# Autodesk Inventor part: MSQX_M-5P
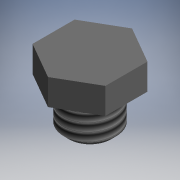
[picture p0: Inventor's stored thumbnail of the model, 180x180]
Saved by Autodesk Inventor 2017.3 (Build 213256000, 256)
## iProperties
Part Number: MSQX_M-5P
Material: Generic
Catalog Web Link: www.cadenas.de
Description: MSQX M-5P-Low-Speed Rotary Table Rack & Pinion Style
Vendor: SMC
Document SubType Name: Modeling
Designer: partserver
Manufacturer: SMC
Mass: 0.178699 g
Surface Area: 1.99414 cm^2
Volume: 0.178699 cm^3
Density: 1 g/cm^3
Appearance: PSOLRGB-128-128-128
Category: PARTsolutions
Company: SMC
Title: M-5P
Author: Cadenas PARTsolutions
Comments: Low-Speed Rotary Table Rack & Pinion Style
PSOL_IDENT_0: {$CADENAS_DATA\23d-libs\smc_jp\actuator\rotary_actuator\msqx\parts\msqx_5p.prj},156 {VTYP=3D},{NB=MS
PSOL_IDENT_1: QX_M-5P},{LINA=M-5P},{NN=MSQX M-5P},{DATE=09.12.2020 02:49:37},{GEOMDATE=19.01.2011 08:34:00},{VERSI
PSOL_IDENT_2: ON=},{LINEID=10},{WBVAR=},{WBNUMERIC=}  {NB=MSQX_M-5P},{LINA=M-5P},{KT=DUMMY},{MODEL=M-5P}
NB: MSQX_M-5P
NN: MSQX M-5P
NT: Low-Speed Rotary Table Rack & Pinion Style
NBSYN: MSQX_$MODEL.
LINA: M-5P
CATALOG: SMC (JP
MODEL: M-5P
SUPPLIER: SMC
ARTICLENO: MSQX_M-5P
BOMINFO: M-5P
CREATOR: CADENAS GmbH
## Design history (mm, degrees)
sketch "Sketch_1"
  geometry: L1 (-3.5, -2.021)-(0, -4.041); L2 (0, -4.041)-(3.5, -2.021); L3 (3.5, -2.021)-(3.5, 2.021); L4 (3.5, 2.021)-(0, 4.041); L5 (0, 4.041)-(-3.5, 2.021); L6 (-3.5, 2.021)-(-3.5, -2.021)
  constraints: 12 end point
extrude "Extrusion1" join sketch "Sketch_1" distance "d0" = 2.7; taper "d1" = 0 deg
sketch "Sketch_4"
  geometry: C1 r 5 at (0, 0); C2 r 3 at (0, 0); 2 further points
  constraints: 2 centre point
extrude "Extrusion2" cut sketch "Sketch_4" distance "d2" = 0.2; taper "d3" = 0 deg
sketch "Sketch_2"
  geometry: L1 (0, 0)-(0, 3.5); L2 (0, 3.5)-(2.01, 3.5); L3 (2.01, 3.5)-(2.5, 3.01); L4 (2.5, 3.01)-(2.5, 0); L5 (2.5, 0)-(0, 0); L6 (0, 0)-(0, 3.5)
  constraints: 12 end point
revolve "Revolution1" sketch "Sketch_2" stored, may be unused: angle "d4" = 360 deg
thread "Thread1" dims "d5" = 3.0095, "d6" = 0
node "plug_body_XY"
node "plug_body_YZ"
node "plug_body_ZX"
node "plug_body_X"
node "plug_body_Y"
node "plug_body_Z"
node "plug_body_Center"
body "Solid1"
other parameters: "d7" = 0
